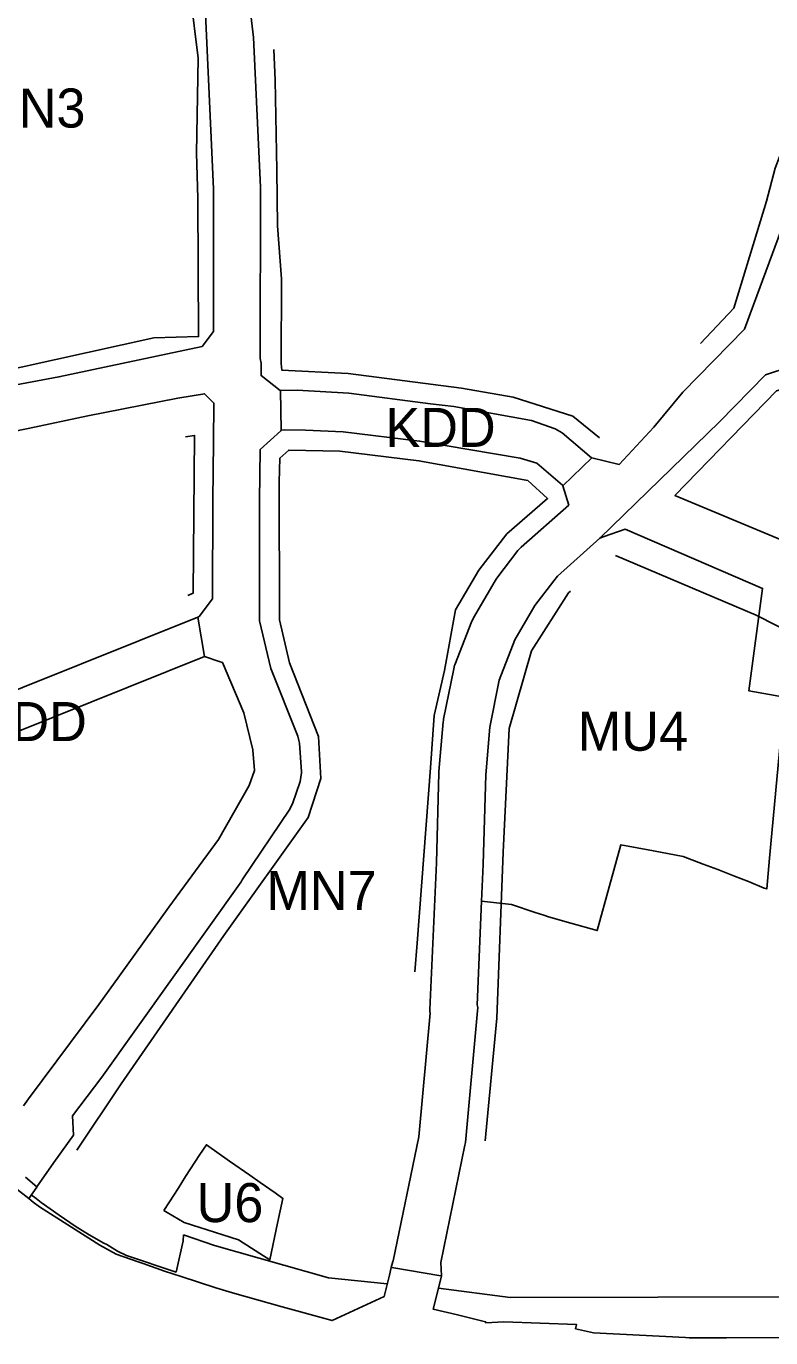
# Model space of a CAD drawing. Extents: x 7425930 to 7427318, y 5544765 to 5546387.
# Drawn here: x 7426645.2 to 7426835.8, y 5545460.2 to 5545796 of the extents above; entities that cross this region are included whole.
import ezdxf

# ---------------------------------------------------------------- set-up
doc = ezdxf.new("R2010")
doc.units = 0
for name, color, linetype in [('linie_rozgraniczajace', 7, 'Continuous'), ('linie_zabudowy_nieprzekraczalne', 7, 'Continuous'), ('linie_zabudowy_obowiazujace', 7, 'Continuous'), ('oznaczenia_przeznaczen', 7, 'Continuous')]:
    doc.layers.add(name, color=color, linetype=linetype)

msp = doc.modelspace()

# ---------------------------------------------------------------- linework, layer by layer
at = {"layer": 'linie_rozgraniczajace'}
for points in [[(7426702.28, 5545802.62), (7426703.39, 5545793.14), (7426705.16, 5545754.8), (7426705.13, 5545754.66), (7426705.16, 5545754.52), (7426705.11, 5545710.99), (7426705.11, 5545710.97), (7426705.37, 5545709.75), (7426705.34, 5545706.56), (7426710.27, 5545702.7), (7426710.34, 5545702.7), (7426710.53, 5545692.62), (7426710.51, 5545692.62), (7426710.36, 5545692.45), (7426705.12, 5545687.66), (7426704.95, 5545674.54), (7426704.91, 5545643.77), (7426707.83, 5545631.52), (7426714.74, 5545614.2), (7426714.97, 5545613.14), (7426715.15, 5545612.44), (7426715.72, 5545605.05), (7426715.7, 5545604.94), (7426715.73, 5545604.83), (7426715.39, 5545602.59), (7426713.37, 5545596.86), (7426713.35, 5545596.83), (7426713.34, 5545596.79), (7426712.69, 5545595.5), (7426700.48, 5545577.4), (7426700.24, 5545576.95), (7426664.53, 5545526.93), (7426657.06, 5545516.95), (7426657.29, 5545512.05), (7426655.76, 5545509.89), (7426652.32, 5545505.01), (7426647.96, 5545498.81), (7426645.06, 5545501.29)], [(7426840.91, 5545750.25), (7426829.1, 5545718.41), (7426813.32, 5545702.28), (7426805.94, 5545693.39), (7426797.07, 5545683.83), (7426790.07, 5545685.47), (7426789.98, 5545685.48), (7426782.4, 5545691.94), (7426780.64, 5545692.92), (7426774.59, 5545695.06), (7426754.72, 5545698.62), (7426748.74, 5545699.31), (7426727.84, 5545702.03), (7426714.57, 5545702.82), (7426710.34, 5545702.7), (7426710.27, 5545702.7), (7426705.34, 5545706.56), (7426705.37, 5545709.75), (7426705.11, 5545710.97), (7426705.11, 5545710.99), (7426705.16, 5545754.52), (7426705.13, 5545754.66), (7426705.16, 5545754.8), (7426703.39, 5545793.14), (7426702.28, 5545802.62)], [(7426573.97, 5545674.14), (7426568.96, 5545685.11), (7426581.57, 5545689.43), (7426590.07, 5545692.34), (7426590.17, 5545692.35), (7426590.38, 5545692.43), (7426597.17, 5545694.36), (7426611.06, 5545698.3), (7426611.35, 5545698.35), (7426611.6, 5545698.43), (7426653.57, 5545706.21), (7426690.23, 5545714.04), (7426693.12, 5545717.84), (7426693.16, 5545754.39), (7426691.09, 5545799.24)], [(7426691.09, 5545799.24), (7426693.16, 5545754.39), (7426693.12, 5545717.84), (7426690.23, 5545714.04), (7426653.57, 5545706.21), (7426611.6, 5545698.43)], [(7426840.69, 5545708.83), (7426834.5, 5545706.76), (7426822.71, 5545694.72), (7426792.07, 5545664.95), (7426781.27, 5545655.23), (7426780.29, 5545654), (7426775.45, 5545647.66), (7426770.32, 5545638.89), (7426766.32, 5545628.6), (7426763.89, 5545616.55), (7426762.86, 5545604.31), (7426762.21, 5545581.42), (7426762.21, 5545581.4), (7426762.21, 5545581.32), (7426761.8, 5545571.92), (7426760.63, 5545545.39), (7426760.8, 5545544.7), (7426760.78, 5545543.9), (7426757.65, 5545510.15), (7426757.58, 5545509.84), (7426757.55, 5545509.48), (7426751.33, 5545479.46), (7426751.58, 5545475.99), (7426751.37, 5545476.02), (7426738.8, 5545478.11), (7426738.68, 5545478.13), (7426738.68, 5545478.14), (7426739.05, 5545479.65), (7426739.16, 5545479.88), (7426745.73, 5545511.59), (7426748.67, 5545543.26), (7426748.57, 5545543.68), (7426748.57, 5545544.18), (7426750.22, 5545581.8), (7426750.87, 5545604.82), (7426750.88, 5545604.88), (7426750.89, 5545605.15), (7426751.96, 5545617.9), (7426752.02, 5545618.21), (7426752.06, 5545618.59), (7426754.66, 5545631.48), (7426754.91, 5545632.36), (7426754.94, 5545632.41), (7426754.95, 5545632.47), (7426759.31, 5545643.69), (7426759.35, 5545643.75), (7426759.72, 5545644.54), (7426765.28, 5545654.04), (7426765.57, 5545654.42), (7426765.69, 5545654.65), (7426771.11, 5545661.75), (7426771.47, 5545662.18), (7426771.91, 5545662.61), (7426784.14, 5545673.38), (7426782.62, 5545678.34), (7426790.07, 5545685.47), (7426797.07, 5545683.83), (7426805.94, 5545693.39), (7426813.32, 5545702.28), (7426829.1, 5545718.41), (7426840.91, 5545750.25)], [(7426897.61, 5545460.33), (7426824.49, 5545460.15), (7426822.75, 5545460.15), (7426814.94, 5545460.17), (7426814.04, 5545460.22), (7426790.47, 5545461.44), (7426785.86, 5545462.48), (7426786.07, 5545463.59), (7426767.47, 5545464.27), (7426762.92, 5545463.98), (7426762.81, 5545464.27), (7426755.6, 5545466), (7426749.39, 5545467.48), (7426750.16, 5545470.47), (7426751.58, 5545475.99), (7426751.33, 5545479.46), (7426757.55, 5545509.48), (7426757.58, 5545509.84), (7426757.65, 5545510.15), (7426760.78, 5545543.9), (7426760.8, 5545544.7), (7426760.63, 5545545.39), (7426761.8, 5545571.92), (7426769.48, 5545571.14), (7426775.54, 5545569.09), (7426777.77, 5545568.34), (7426778.93, 5545567.99), (7426784.69, 5545566.35), (7426791.42, 5545564.44), (7426794.55, 5545575.89), (7426797.43, 5545586.38), (7426805.8, 5545584.81), (7426813.41, 5545583.39), (7426818.54, 5545581.47), (7426822.28, 5545580.07), (7426826.56, 5545578.4), (7426830.11, 5545576.97), (7426834.17, 5545575.33), (7426834.8, 5545575.08), (7426835.5, 5545583.01), (7426839.39, 5545624.21), (7426830.19, 5545625.83), (7426833.75, 5545652.04), (7426798.57, 5545667.2), (7426793.22, 5545665.39), (7426792.07, 5545664.95), (7426822.71, 5545694.72), (7426834.5, 5545706.76), (7426840.69, 5545708.83)], [(7426625.93, 5545688.96), (7426645.7, 5545693.04), (7426661.02, 5545696.22), (7426684.04, 5545700.8), (7426690.87, 5545701.91), (7426693.26, 5545699.52), (7426693.14, 5545689.49), (7426692.95, 5545674.66), (7426692.96, 5545674.63), (7426692.95, 5545674.59), (7426692.92, 5545649.41), (7426689.49, 5545644.83), (7426689.19, 5545644.7), (7426614.38, 5545614.72)], [(7426644.51, 5545519.55), (7426645.78, 5545521.33), (7426663.78, 5545545.53), (7426669.07, 5545552.88), (7426681.7, 5545570.42), (7426694.45, 5545587.76), (7426702.31, 5545601.57), (7426703.66, 5545605.39), (7426703.26, 5545610.61), (7426703.23, 5545610.69), (7426700.97, 5545620.17), (7426695.46, 5545633.07), (7426694.85, 5545633.27), (7426690.9, 5545634.6), (7426689.19, 5545644.7), (7426689.49, 5545644.83), (7426692.92, 5545649.41), (7426692.95, 5545674.59), (7426692.96, 5545674.63), (7426692.95, 5545674.66), (7426693.14, 5545689.49), (7426693.26, 5545699.52), (7426690.87, 5545701.91), (7426684.04, 5545700.8), (7426661.02, 5545696.22), (7426645.7, 5545693.04), (7426625.93, 5545688.96)], [(7426622.62, 5545607.25), (7426690.87, 5545634.61), (7426690.9, 5545634.6), (7426694.85, 5545633.27), (7426695.46, 5545633.07), (7426700.97, 5545620.17), (7426703.23, 5545610.69), (7426703.26, 5545610.61), (7426703.66, 5545605.39), (7426702.31, 5545601.57), (7426694.45, 5545587.76), (7426681.7, 5545570.42), (7426669.07, 5545552.88), (7426663.78, 5545545.53), (7426645.78, 5545521.33), (7426644.51, 5545519.55)], [(7426645.06, 5545501.29), (7426647.96, 5545498.81), (7426647.92, 5545498.76), (7426645.86, 5545495.83), (7426645.86, 5545495.82), (7426642.85, 5545498.19)], [(7426642.85, 5545498.19), (7426645.86, 5545495.82), (7426647.02, 5545494.91), (7426648.6, 5545493.67), (7426664.05, 5545483.9), (7426668.2, 5545481.59), (7426673.84, 5545479.61), (7426675.18, 5545479.14), (7426680.65, 5545477.22), (7426684.86, 5545475.8), (7426693.78, 5545472.97), (7426698.06, 5545471.63), (7426701.32, 5545470.71), (7426710.78, 5545468.04), (7426723.56, 5545464.54), (7426736.84, 5545470.68)], [(7426736.84, 5545470.68), (7426738.2, 5545476.2), (7426738.68, 5545478.13), (7426738.8, 5545478.11), (7426751.37, 5545476.02), (7426751.58, 5545475.99), (7426750.16, 5545470.47), (7426749.39, 5545467.48), (7426755.6, 5545466), (7426762.81, 5545464.27), (7426762.92, 5545463.98), (7426767.47, 5545464.27), (7426786.07, 5545463.59), (7426785.86, 5545462.48), (7426790.47, 5545461.44), (7426814.04, 5545460.22), (7426814.94, 5545460.17), (7426822.75, 5545460.15), (7426824.49, 5545460.15), (7426897.61, 5545460.33)]]:
    msp.add_lwpolyline(points, dxfattribs=at)
for points in [[(7426710.53, 5545692.62), (7426710.34, 5545702.7), (7426714.57, 5545702.82), (7426727.84, 5545702.03), (7426748.74, 5545699.31), (7426754.72, 5545698.62), (7426774.59, 5545695.06), (7426780.64, 5545692.92), (7426782.4, 5545691.94), (7426789.98, 5545685.48), (7426790.07, 5545685.47), (7426782.62, 5545678.34), (7426782.55, 5545678.53), (7426775.96, 5545684.13), (7426771.67, 5545685.41), (7426745.94, 5545689.79), (7426726.39, 5545692.18), (7426716.7, 5545692.58), (7426711.41, 5545692.63)], [(7426645.86, 5545495.82), (7426645.86, 5545495.83), (7426647.92, 5545498.76), (7426647.96, 5545498.81), (7426652.32, 5545505.01), (7426655.76, 5545509.89), (7426657.29, 5545512.05), (7426657.06, 5545516.95), (7426664.53, 5545526.93), (7426700.24, 5545576.95), (7426700.48, 5545577.4), (7426712.69, 5545595.5), (7426713.34, 5545596.79), (7426713.35, 5545596.83), (7426713.37, 5545596.86), (7426715.39, 5545602.59), (7426715.73, 5545604.83), (7426715.7, 5545604.94), (7426715.72, 5545605.05), (7426715.15, 5545612.44), (7426714.97, 5545613.14), (7426714.74, 5545614.2), (7426707.83, 5545631.52), (7426704.91, 5545643.77), (7426704.95, 5545674.54), (7426705.12, 5545687.66), (7426710.36, 5545692.45), (7426710.51, 5545692.62), (7426710.53, 5545692.62), (7426711.41, 5545692.63), (7426716.7, 5545692.58), (7426726.39, 5545692.18), (7426745.94, 5545689.79), (7426771.67, 5545685.41), (7426775.96, 5545684.13), (7426782.55, 5545678.53), (7426782.62, 5545678.34), (7426784.14, 5545673.38), (7426771.91, 5545662.61), (7426771.47, 5545662.18), (7426771.11, 5545661.75), (7426765.69, 5545654.65), (7426765.57, 5545654.42), (7426765.28, 5545654.04), (7426759.72, 5545644.54), (7426759.35, 5545643.75), (7426759.31, 5545643.69), (7426754.95, 5545632.47), (7426754.94, 5545632.41), (7426754.91, 5545632.36), (7426754.66, 5545631.48), (7426752.06, 5545618.59), (7426752.02, 5545618.21), (7426751.96, 5545617.9), (7426750.89, 5545605.15), (7426750.88, 5545604.88), (7426750.87, 5545604.82), (7426750.22, 5545581.8), (7426748.57, 5545544.18), (7426748.57, 5545543.68), (7426748.67, 5545543.26), (7426745.73, 5545511.59), (7426739.16, 5545479.88), (7426739.05, 5545479.65), (7426738.68, 5545478.14), (7426738.68, 5545478.13), (7426738.2, 5545476.2), (7426736.84, 5545470.68), (7426723.56, 5545464.54), (7426710.78, 5545468.04), (7426701.32, 5545470.71), (7426698.06, 5545471.63), (7426693.78, 5545472.97), (7426684.86, 5545475.8), (7426680.65, 5545477.22), (7426675.18, 5545479.14), (7426673.84, 5545479.61), (7426668.2, 5545481.59), (7426664.05, 5545483.9), (7426648.6, 5545493.67), (7426647.02, 5545494.91)], [(7426761.8, 5545571.92), (7426762.21, 5545581.32), (7426762.21, 5545581.4), (7426762.21, 5545581.42), (7426762.86, 5545604.31), (7426763.89, 5545616.55), (7426766.32, 5545628.6), (7426770.32, 5545638.89), (7426775.45, 5545647.66), (7426780.29, 5545654), (7426781.27, 5545655.23), (7426792.07, 5545664.95), (7426793.22, 5545665.39), (7426798.57, 5545667.2), (7426833.75, 5545652.04), (7426830.19, 5545625.83), (7426839.39, 5545624.21), (7426835.5, 5545583.01), (7426834.8, 5545575.08), (7426834.17, 5545575.33), (7426830.11, 5545576.97), (7426826.56, 5545578.4), (7426822.28, 5545580.07), (7426818.54, 5545581.47), (7426813.41, 5545583.39), (7426805.8, 5545584.81), (7426797.43, 5545586.38), (7426794.55, 5545575.89), (7426791.42, 5545564.44), (7426784.69, 5545566.35), (7426778.93, 5545567.99), (7426777.77, 5545568.34), (7426775.54, 5545569.09), (7426769.48, 5545571.14)], [(7426611.24, 5545609.87), (7426611.54, 5545611.8), (7426612.56, 5545613.46), (7426614.14, 5545614.61), (7426614.27, 5545614.65), (7426614.38, 5545614.72), (7426689.19, 5545644.7), (7426690.9, 5545634.6), (7426690.87, 5545634.61), (7426622.62, 5545607.25), (7426630.29, 5545586.51), (7426621.08, 5545582.66), (7426621.07, 5545582.67), (7426620.92, 5545583.04), (7426611.55, 5545608.34)], [(7426680.46, 5545492.77), (7426681.3, 5545492.27), (7426681.32, 5545492.25), (7426685.62, 5545489.65), (7426699.58, 5545485.2), (7426705, 5545481.74), (7426707.57, 5545480.1), (7426709.58, 5545489.53), (7426710.92, 5545495.84), (7426708.93, 5545497.24), (7426705.12, 5545499.92), (7426702.47, 5545501.77), (7426697.29, 5545505.41), (7426691.36, 5545509.58), (7426689.68, 5545507.1), (7426686.03, 5545501.43), (7426684.09, 5545498.41), (7426681.86, 5545494.95), (7426680.46, 5545492.78)], [(7426680.46, 5545492.77), (7426680.46, 5545492.78), (7426681.86, 5545494.95), (7426684.09, 5545498.41), (7426686.03, 5545501.43), (7426689.68, 5545507.1), (7426691.36, 5545509.58), (7426697.29, 5545505.41), (7426702.47, 5545501.77), (7426705.12, 5545499.92), (7426708.93, 5545497.24), (7426710.92, 5545495.84), (7426709.58, 5545489.53), (7426707.57, 5545480.1), (7426705, 5545481.74), (7426699.58, 5545485.2), (7426685.62, 5545489.65), (7426681.32, 5545492.25), (7426681.3, 5545492.27)]]:
    msp.add_lwpolyline(points, close=True, dxfattribs=at)
at = {"layer": 'linie_zabudowy_nieprzekraczalne'}
for points in [[(7426817.83, 5545714.78), (7426826.37, 5545723.84), (7426834.78, 5545751.26), (7426836.93, 5545759.67), (7426846.96, 5545785.83), (7426853.37, 5545806.21), (7426861.65, 5545834.56), (7426862.63, 5545841.81), (7426862.59, 5545856.37), (7426862.87, 5545892), (7426860.69, 5545913.21), (7426856.61, 5545925.78), (7426855.16, 5545931.8), (7426839.28, 5545925.06), (7426823.82, 5545917.81), (7426815.07, 5545911.63), (7426803.33, 5545903.3), (7426787.32, 5545894.35)], [(7426569.69, 5545690.72), (7426587.81, 5545695.73), (7426606.67, 5545700.62), (7426616.7, 5545703.11), (7426635.7, 5545706.93), (7426677.92, 5545716.2), (7426689.33, 5545716.53), (7426689.12, 5545752.02), (7426688.79, 5545763.54), (7426689.21, 5545787.87), (7426687.3, 5545803.81), (7426682.63, 5545830.15), (7426680.5, 5545841.74), (7426673, 5545873.88), (7426664.59, 5545872.76), (7426637.08, 5545872.3), (7426614.1, 5545874.15), (7426585.78, 5545881.94), (7426534.93, 5545898.54), (7426528.78, 5545897.54)], [(7426708.59, 5545790.04), (7426708.98, 5545782.22), (7426709.34, 5545759.19), (7426709.55, 5545744.88), (7426710.58, 5545731.36), (7426710.53, 5545709.66), (7426710.65, 5545707.95), (7426727.64, 5545707.06), (7426756.66, 5545703.38), (7426769.93, 5545701), (7426785.14, 5545696.15), (7426792.02, 5545690.63)], [(7426876.75, 5545704.54), (7426867.16, 5545705.82), (7426852.17, 5545703.98), (7426841.25, 5545703.78), (7426837.32, 5545702.69), (7426811.3, 5545675.88), (7426838.51, 5545664.49), (7426860.23, 5545652.73), (7426900.71, 5545611.21), (7426901.45, 5545590.07), (7426901.26, 5545577.4), (7426902.91, 5545542.39), (7426903.95, 5545519.93), (7426946.89, 5545518.89), (7426956.59, 5545509.68), (7426958.18, 5545470.69)], [(7426686.59, 5545650.22), (7426687.94, 5545650.83), (7426688.3, 5545691.26), (7426685.99, 5545690.84)], [(7426744.7, 5545553.89), (7426745.35, 5545561.23), (7426748.74, 5545606.1), (7426749.66, 5545619.49), (7426752.32, 5545631.01), (7426755.13, 5545646.53), (7426761.07, 5545656.7), (7426768.31, 5545666.07), (7426778.71, 5545675.1), (7426773.63, 5545679.66), (7426745.75, 5545684.75), (7426725.53, 5545687.24), (7426712.41, 5545687.5), (7426710.11, 5545685.4), (7426709.98, 5545679.26), (7426710.09, 5545644.04), (7426712.65, 5545633.03), (7426720.04, 5545614.13), (7426720.67, 5545603.36), (7426717.44, 5545593.37), (7426695.79, 5545563.21), (7426669.49, 5545525.18), (7426658.19, 5545508.19)], [(7426938.12, 5545470.74), (7426936.85, 5545501.94), (7426893.04, 5545502.57), (7426884.3, 5545509.8), (7426883.08, 5545541.59), (7426883.51, 5545581.65), (7426882.07, 5545602.45), (7426847.55, 5545637.32), (7426832.14, 5545645.17), (7426796.12, 5545660.5)], [(7426784.61, 5545651.34), (7426784.08, 5545650.89), (7426774.62, 5545636.07), (7426768.88, 5545616.18), (7426767.31, 5545584.54), (7426765.73, 5545541.98), (7426762.74, 5545510.55)]]:
    msp.add_lwpolyline(points, dxfattribs=at)
at = {"layer": 'linie_zabudowy_obowiazujace'}
for points in [[(7426646.51, 5545496.75), (7426647.77, 5545495.78), (7426649.07, 5545494.79), (7426653.66, 5545491.59), (7426657.77, 5545488.76), (7426661.29, 5545486.55), (7426665.09, 5545484.42), (7426665.82, 5545484.02), (7426668.6, 5545482.34), (7426670.91, 5545481.26), (7426683.59, 5545476.98), (7426685.42, 5545484.94), (7426685.49, 5545486.48)], [(7426685.5, 5545486.5), (7426693.39, 5545483.81), (7426722.59, 5545475.46), (7426737.67, 5545473.98)], [(7426750.75, 5545472.83), (7426769.13, 5545470.46), (7426882.45, 5545470.69), (7426938.05, 5545470.71)]]:
    msp.add_lwpolyline(points, dxfattribs=at)

# ---------------------------------------------------------------- texts
at = {"layer": 'oznaczenia_przeznaczen'}
for s, p in [('MN3', (7426632.15, 5545770.08)), ('KDD', (7426737.18, 5545688.3)), ('KDD', (7426632.51, 5545612.96)), ('MU4', (7426786.43, 5545610.49)), ('MN7', (7426706.69, 5545569.71)), ('U6', (7426688.83, 5545489.76))]:
    msp.add_text(s, height=10, dxfattribs=at).set_placement(p)

doc.saveas('drawing.dxf')
